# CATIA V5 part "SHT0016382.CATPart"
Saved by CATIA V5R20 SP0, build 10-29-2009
Part number: SHT0016382
Bounding box of the stored display mesh (mm): x -453 to 31, y 582 to 876, z 0.9 to 38.4
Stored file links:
  G:\冉\工作2022.11.18周五下午\6.张甲\3.A6\9.25  底支架2D图纸\2D\宽车副驾底支架\SHT0016382-A6宽车副司机座椅底支架上板\SHT0016382.CATPart
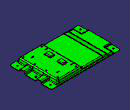
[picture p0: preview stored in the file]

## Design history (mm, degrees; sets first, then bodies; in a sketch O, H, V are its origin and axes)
Body1
  Solid1: solid without history
Body2 (main body)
